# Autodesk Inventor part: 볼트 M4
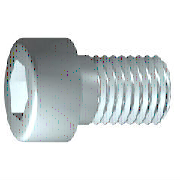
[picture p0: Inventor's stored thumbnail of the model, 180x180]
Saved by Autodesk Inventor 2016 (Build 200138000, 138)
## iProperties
IsCustomPart: 0
Created: 2012-02
Part Number: 볼트 M4
Material: 스테인리스강
Description: 6각 소켓 머리 캡 나사
Document SubType Name: Modeling
Standard: ISO 4762
Designer: mduedu
Standard Revision: Fourth edition 2004-03-01
Standards Organization: ISO
Language: ko-KR
Size Designation: M4 x 12
Categories: <MemberInstance><Categories><Category DisplayName="조임쇠" InternalName="e4da775c-781d-43d5-af7c-5136215cf5a6" Mnemonic="FSTN"><Category DisplayName="볼트" InternalN
Density: 8.08 g/cm^3
Appearance: 반광택
Mass: 2.2972 g
Surface Area: 3.30853 cm^2
Volume: 0.284306 cm^3
Author: mduedu
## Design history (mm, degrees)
sketch "스케치1"
  geometry: L1 (-1, 0)-(12, 0); L2 (12, 0)-(12, 2); L3 (12, 2)-(1.75, 2); L4 (1.75, 2)-(1.32, 2); L5 (1.32, 2)-(0, 2); L6 (0, 2)-(0, 3.5); L7 (0, 3.5)-(-4, 3.5); L8 (-4, 3.5)-(-4, 1.732); L9 (-4, 1.732)-(-2, 1.732); L10 (-2, 1.732)-(-1, 0); L11 (-7.2, 0)-(15.2, 0) reference; L12 (0, -0.7)-(0, 4.2) reference; L13 (1.75, 2)-(0, 2)
  constraints: 22 end point, 6 parallel, 2 collinear, 2 perpendicular, 1 horizontal, 1 point on line
  dimensions: "d1" = 10.25 distance from line of L3.end L2 (= GEL); "d2" = 0.42952 distance of L4.end L3.end (computed from GAL); "d3" = 4 distance between parallel lines of L8 L6 (= KOH); "d4" = 2 distance of L8.end L9.end (= INTI); "d5" = 60 deg angle of L10 L1; "d6" = 4 diameter of L3 L1 (= GD); "d7" = 4 diameter of L5 L1 (= BDM); "d8" = 3.4641 diameter of L9 L1 (= 1.1547 x SW); "d9" = 7 diameter of L7 L1 (= KOD); "d26" = 12 distance between parallel lines of L12 L2 (= NLG)
revolve "본체" sketch "스케치1" stored, may be unused: angle "d10" = 90 deg
sketch "스케치2"
  geometry: L1 (0, -4.9)-(0, 4.9) reference; L2 (-4.9, 0)-(4.9, 0) reference; L3 (1.732, 0)-(0.866, -1.5); L4 (0.866, -1.5)-(-0.866, -1.5); L5 (-0.866, -1.5)-(-1.732, 0); L6 (-1.732, 0)-(-0.866, 1.5); L7 (-0.866, 1.5)-(0.866, 1.5); L8 (0.866, 1.5)-(1.732, 0); 2 further points
  constraints: 12 end point, 1 coincident, 1 horizontal alignment, 1 point on line, 12 other
extrude "슬롯" join sketch "스케치2" stored distance "d11" = 10; taper "d12" = 0 deg
workplane "Work Plane1"
fillet "Fillet2" dims "d30" = 0.1 (= R)
body "Solid1"
fillet "모깎기1" dims "d17" = 0.4 (= RR)
feature "스레드" dims "d13" = 10.25 (= GEL), "d14" = 0
chamfer "모따기1" distance "d15" = 0.42941 (= -0.5 x SPD + 0.5 x GD); stored, may be unused: second distance "d16" = 0.42941 (= GUL), angle "d27" = 45 deg
other parameters: "GD" = 4 [user parameter; used in 2 equation terms], "NLG" = 12 [user parameter; used in 1 equation term], "GEL" = 10.25 [user parameter; used in 2 equation terms], "KOD" = 7 [user parameter; used in 1 equation term], "KOH" = 4 [user parameter; used in 1 equation term], "INTI" = 2 [user parameter; used in 1 equation term], "GAL" = 0.42941 (= 0.61345 x PTC) [user parameter; used in 1 equation term], "GUL" = 0.42941 (= 0.61345 x PTC) [user parameter; used in 1 equation term], "BDM" = 4 (= NND) [user parameter; used in 1 equation term], "SW" = 3 [user parameter; used in 2 equation terms], "RR" = 0.4 [user parameter; used in 1 equation term], "SPD" = 3.14117 (= NND - 1.2269 x PTC) [user parameter; used in 1 equation term], "d19" = 0, "d28" = 0, "d29" = 0, "R" = 0.1 [user parameter; used in 1 equation term], "TOA" = 30 deg [user parameter], "GD1" = 3.14117 (= THREADDIA - 1.2269 x PTC) [user parameter], "THREADDIA" = 4 [user parameter; used in 1 equation term], "FAWI" = 45 deg [user parameter], "TPU" = 14.28571 (computed from PTC) [user parameter], "PTC" = 0.7 [user parameter; used in 5 equation terms], "NND" = 4 [user parameter; used in 2 equation terms], "E0" = 3.465 (= 1.155 x SW) [user parameter]
